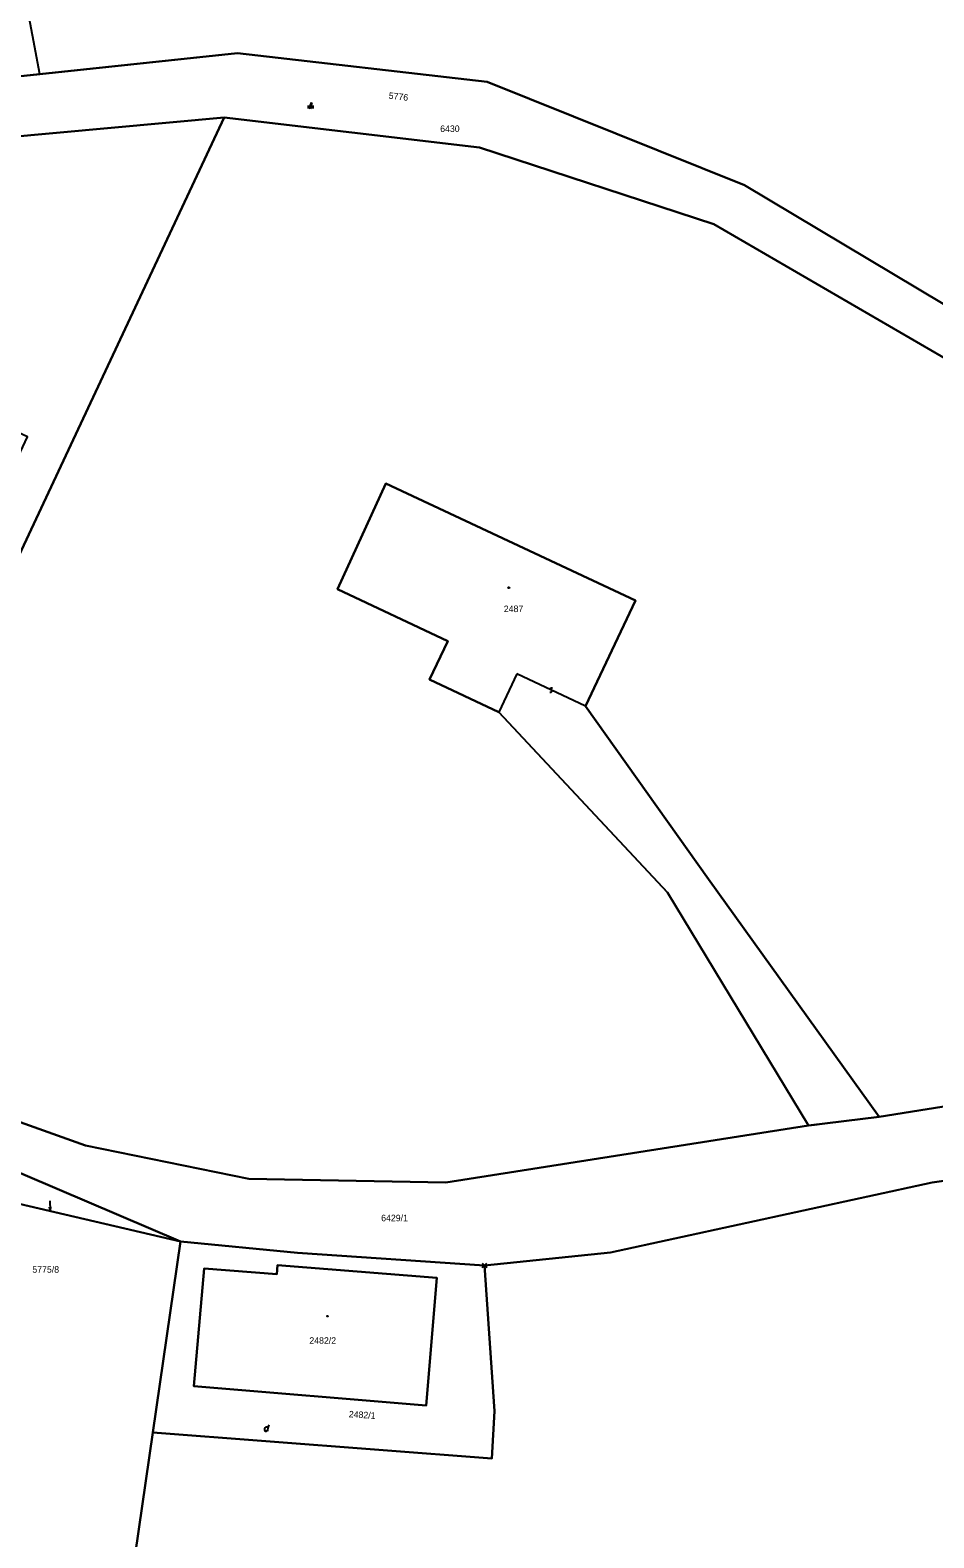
# Model space of a CAD drawing. Extents: x -439750 to -439180, y -1258684 to -1258308.
# Drawn here: x -439470.2 to -439415, y -1258449.2 to -1258356.9 of the extents above; entities that cross this region are included whole.
import ezdxf

# ---------------------------------------------------------------- set-up
doc = ezdxf.new("R2010")
doc.units = 0
doc.layers.add('KATASTER', color=7, linetype='Continuous')
doc.layers.add('UOV', color=7, linetype='Continuous')

# ---------------------------------------------------------------- blocks, each defined once
blk = doc.blocks.new('402')
blk.add_lwpolyline([(0.09, 0.15), (0.18, 0), (0.09, -0.15), (-0.09, -0.15), (-0.18, 0), (-0.09, 0.15), (0.09, 0.15)])
blk = doc.blocks.new('CESTA')
for p, q in [((-0.32, 0.8), (-1, 0.8)), ((-1, 0.4), (-0.46, 0.4)), ((0.1, 2), (-0.6, 0)), ((-0.1, 0), (0.5, 2)), ((0.02, 0.4), (1, 0.4)), ((1, 0.8), (0.14, 0.8))]:
    blk.add_line(p, q)
blk = doc.blocks.new('SIPKA_2')
blk.add_line((-0.2, 2), (0, 3))
blk.add_lwpolyline([(0, 0), (0, 3), (0.2, 2)])
blk = doc.blocks.new('POINT_DISPLAY')
for p, q in [((-0.14, -0.14), (0.14, 0.14)), ((-0.14, 0.14), (0.14, -0.14))]:
    blk.add_line(p, q)
blk = doc.blocks.new('DVUR')
blk.add_line((0.63, 0.99), (0.9, 1.89))
blk.add_lwpolyline([(0.45, 0), (0.45, 0.27), (0.63, 0.99), (0.54, 1.17), (0.36, 1.26), (0.09, 1.26), (-0.18, 1.17), (-0.36, 0.99), (-0.54, 0.72), (-0.54, 0.36), (-0.45, 0.09), (-0.27, 0), (0, 0), (0.18, 0.09), (0.45, 0.27)])
blk = doc.blocks.new('2182')
blk.add_lwpolyline([(0.05, 0.75), (-0.26, 0.64), (-0.37, 0.34), (-0.23, 0.09), (0.27, -0.11), (0.37, -0.41), (0.21, -0.68), (-0.05, -0.75)])

msp = doc.modelspace()

# ---------------------------------------------------------------- linework, layer by layer
at = {"layer": 'KATASTER'}
for p, q in [((-439469.66, -1258359.58), (-439478.63, -1258311.39)), ((-439440.46, -1258396.29), (-439441.57, -1258398.64)), ((-439436.27, -1258398.27), (-439440.46, -1258396.29))]:
    msp.add_line(p, q, dxfattribs=at)
for points in [[(-439415.15, -1258317.05), (-439391.19, -1258328.53), (-439365.48, -1258348.34), (-439361.22, -1258351.62), (-439366.64, -1258358.17), (-439385.11, -1258380.51), (-439389.09, -1258387.3), (-439402.31, -1258380.87), (-439394.11, -1258375.22), (-439388.96, -1258369.12), (-439401.08, -1258358.06), (-439403.77, -1258355.61), (-439406.89, -1258360.91), (-439411.07, -1258358.61), (-439413.17, -1258361.96), (-439408.96, -1258364.43), (-439414.38, -1258373.64), (-439426.53, -1258366.38)], [(-439583.01, -1258405.44), (-439529.05, -1258372.98), (-439510.66, -1258363.93), (-439469.66, -1258359.58), (-439457.56, -1258358.3), (-439442.28, -1258360.05), (-439426.53, -1258366.38), (-439414.38, -1258373.64), (-439402.31, -1258380.87), (-439389.09, -1258387.3), (-439380.93, -1258392.19), (-439379.33, -1258392.51), (-439372.39, -1258393.61), (-439364.9, -1258394.3), (-439360.22, -1258395.64), (-439331.05, -1258396.01), (-439324.92, -1258395.23), (-439316.1, -1258393.08), (-439301.55, -1258387.38)], [(-439426.53, -1258366.38), (-439442.28, -1258360.05), (-439457.56, -1258358.3), (-439469.66, -1258359.58)], [(-439269.36, -1258377.15), (-439315.05, -1258395.8), (-439324.38, -1258397.9), (-439329.65, -1258398.85), (-439367.83, -1258398.64), (-439381.39, -1258394.16), (-439403.76, -1258383.09), (-439428.41, -1258368.76), (-439442.76, -1258364.07), (-439458.37, -1258362.23), (-439513.27, -1258367.25), (-439515.07, -1258371.54), (-439519.61, -1258372.16), (-439523.86, -1258373.74), (-439527.84, -1258376.06), (-439569.67, -1258401.31)], [(-439569.67, -1258401.31), (-439527.84, -1258376.06), (-439523.86, -1258373.74), (-439519.61, -1258372.16), (-439515.07, -1258371.54), (-439485.92, -1258384.39), (-439474.21, -1258389.89), (-439470.4, -1258381.78), (-439482.06, -1258376.34), (-439485.68, -1258371.89), (-439488.71, -1258370.59), (-439493.04, -1258368.7), (-439513.27, -1258367.25), (-439458.37, -1258362.23), (-439484.43, -1258417.81), (-439506.61, -1258407.45), (-439514.87, -1258403.56), (-439522.96, -1258401.62), (-439530.12, -1258405.09), (-439537.73, -1258410.35), (-439547.65, -1258418.05)], [(-439547.65, -1258418.05), (-439537.73, -1258410.35), (-439527.28, -1258405.47), (-439520.18, -1258404.63), (-439512.57, -1258405.64), (-439506.61, -1258407.45), (-439484.43, -1258417.81), (-439474.81, -1258422.32), (-439466.86, -1258425.16), (-439456.86, -1258427.2), (-439444.81, -1258427.42), (-439422.62, -1258423.93), (-439418.29, -1258423.4), (-439390.34, -1258418.93), (-439355.32, -1258412.49), (-439342.07, -1258411.63), (-439307.35, -1258399.88)], [(-439304.03, -1258403.29), (-439334.89, -1258413.69), (-439341.3, -1258415.85), (-439354.3, -1258417.7), (-439355.78, -1258417.92), (-439355.89, -1258417.18), (-439387.21, -1258424.13), (-439387, -1258423.44), (-439415.05, -1258427.42), (-439434.74, -1258431.72), (-439442.45, -1258432.5), (-439453.89, -1258431.74), (-439461.05, -1258431.03), (-439498.8, -1258414.92), (-439505.79, -1258411.63), (-439510.78, -1258409.92), (-439521.49, -1258405.8), (-439531.73, -1258411.37), (-439536.05, -1258413.64), (-439546.05, -1258421.31)], [(-439472.17, -1258428.45), (-439461.05, -1258431.03), (-439462.74, -1258442.73), (-439465.13, -1258459.21)]]:
    msp.add_lwpolyline(points, dxfattribs=at)
for points in [[(-439418.29, -1258423.4), (-439428.73, -1258408.86), (-439436.27, -1258398.27), (-439433.21, -1258391.81), (-439448.48, -1258384.63), (-439451.43, -1258391.1), (-439444.69, -1258394.29), (-439445.8, -1258396.64), (-439441.57, -1258398.64), (-439431.25, -1258409.67), (-439422.62, -1258423.93), (-439444.81, -1258427.42), (-439456.86, -1258427.2), (-439466.86, -1258425.16), (-439474.81, -1258422.32), (-439484.43, -1258417.81), (-439458.37, -1258362.23), (-439442.76, -1258364.07), (-439428.41, -1258368.76), (-439403.76, -1258383.09), (-439381.39, -1258394.16), (-439367.83, -1258398.64), (-439368.16, -1258411.35), (-439390.34, -1258418.93)], [(-439422.62, -1258423.93), (-439431.25, -1258409.67), (-439441.57, -1258398.64), (-439445.8, -1258396.64), (-439444.69, -1258394.29), (-439451.43, -1258391.1), (-439448.48, -1258384.63), (-439433.21, -1258391.81), (-439436.27, -1258398.27), (-439428.73, -1258408.86), (-439418.29, -1258423.4)], [(-439498.8, -1258414.92), (-439461.05, -1258431.03), (-439472.17, -1258428.45)], [(-439441.83, -1258441.42), (-439442.45, -1258432.5), (-439434.74, -1258431.72), (-439415.05, -1258427.42), (-439387, -1258423.44), (-439387.21, -1258424.13), (-439393.11, -1258458.67), (-439398.93, -1258492.76), (-439399.2, -1258493.87), (-439399.61, -1258493.83), (-439469.01, -1258485.93), (-439465.13, -1258459.21), (-439462.74, -1258442.73), (-439442, -1258444.33)], [(-439442.45, -1258432.5), (-439441.83, -1258441.42), (-439442, -1258444.33), (-439462.74, -1258442.73), (-439461.05, -1258431.03), (-439453.89, -1258431.74)], [(-439455.12, -1258432.48), (-439445.37, -1258433.26), (-439446.01, -1258441.07), (-439460.23, -1258439.89), (-439459.6, -1258432.7), (-439455.16, -1258433.03)], [(-439445.37, -1258433.26), (-439455.12, -1258432.48), (-439455.16, -1258433.03), (-439459.6, -1258432.7), (-439460.23, -1258439.89), (-439446.01, -1258441.07)]]:
    msp.add_lwpolyline(points, close=True, dxfattribs=at)
at = {"layer": 'UOV'}
for points in [[(-439301.55, -1258387.38), (-439316.1, -1258393.08), (-439324.92, -1258395.23), (-439331.05, -1258396.01), (-439360.22, -1258395.64), (-439364.9, -1258394.3), (-439367.7, -1258394.04), (-439372.39, -1258393.61), (-439378.2, -1258389.67), (-439379.33, -1258392.51), (-439380.93, -1258392.19), (-439389.09, -1258387.3), (-439402.31, -1258380.87), (-439414.38, -1258373.64), (-439426.53, -1258366.38), (-439442.28, -1258360.05), (-439457.56, -1258358.3), (-439510.66, -1258363.93), (-439529.05, -1258372.98), (-439583.01, -1258405.44)], [(-439547.65, -1258418.05), (-439537.73, -1258410.35), (-439530.12, -1258405.09), (-439522.96, -1258401.62), (-439514.87, -1258403.56), (-439499.09, -1258410.96), (-439484.43, -1258417.81), (-439474.81, -1258422.32), (-439466.86, -1258425.16), (-439456.86, -1258427.2), (-439444.81, -1258427.42), (-439422.62, -1258423.93), (-439422.26, -1258423.89), (-439421.18, -1258423.75), (-439418.29, -1258423.4), (-439390.34, -1258418.93)], [(-439387, -1258423.44), (-439415.05, -1258427.42), (-439434.74, -1258431.72), (-439442.45, -1258432.5), (-439453.89, -1258431.74), (-439461.05, -1258431.03), (-439498.8, -1258414.92), (-439505.79, -1258411.63), (-439510.78, -1258409.92), (-439521.49, -1258405.8), (-439531.73, -1258411.37), (-439536.05, -1258413.64), (-439546.05, -1258421.31)]]:
    msp.add_lwpolyline(points, dxfattribs=at)
msp.add_lwpolyline([(-439510.66, -1258363.93), (-439457.56, -1258358.3), (-439442.28, -1258360.05), (-439426.53, -1258366.38), (-439414.38, -1258373.64), (-439402.31, -1258380.87), (-439389.09, -1258387.3), (-439380.93, -1258392.19), (-439379.33, -1258392.51), (-439372.39, -1258393.61), (-439367.7, -1258394.04), (-439367.83, -1258398.64), (-439381.39, -1258394.16), (-439403.76, -1258383.09), (-439428.41, -1258368.76), (-439442.76, -1258364.07), (-439458.37, -1258362.23), (-439472.18, -1258363.49), (-439510.27, -1258366.98)], close=True, dxfattribs=at)

# ---------------------------------------------------------------- block references
at = {"layer": 'KATASTER', "xscale": 0.2, "yscale": 0.20000000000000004}
for name, p in [('CESTA', (-439453.08, -1258361.71)), ('402', (-439440.96, -1258391.01)), ('402', (-439452.05, -1258435.61)), ('DVUR', (-439455.8, -1258442.65))]:
    msp.add_blockref(name, p, dxfattribs=at)
at = {"layer": 'KATASTER', "yscale": 0.19999999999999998}
for name, p, xscale, rotation in [('2182', (-439438.365, -1258397.28), 0.2, 154.69860500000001), ('SIPKA_2', (-439469.04, -1258428.54), 0.20000000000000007, -178.77344900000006)]:
    msp.add_blockref(name, p, dxfattribs=dict(at, xscale=xscale, rotation=rotation))
at = {"layer": 'KATASTER'}
msp.add_blockref('POINT_DISPLAY', (-439442.45, -1258432.5), dxfattribs=at)

# ---------------------------------------------------------------- texts
for s, rotation, p in [('5776', 353.801, (-439448.321, -1258361.085)), ('2482/2', 359.989, (-439453.162, -1258437.3)), ('2482/1', 356.38, (-439450.758, -1258441.799))]:
    msp.add_text(s, height=0.4, rotation=rotation, dxfattribs=at).set_placement(p)
for s, p in [('2487', (-439441.262, -1258392.51)), ('5775/8', (-439470.112, -1258432.95))]:
    msp.add_text(s, height=0.4, dxfattribs=at).set_placement(p)
at = {"layer": 'UOV'}
for s, p in [('6430', (-439445.156, -1258363.12)), ('6429/1', (-439448.766, -1258429.8))]:
    msp.add_text(s, height=0.4, dxfattribs=at).set_placement(p)

doc.saveas('drawing.dxf')
